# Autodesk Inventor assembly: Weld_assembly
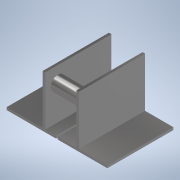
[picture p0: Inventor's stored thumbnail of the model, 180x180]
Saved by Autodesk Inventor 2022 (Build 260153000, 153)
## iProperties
Created: 2016-08
Part Number: Weld_assembly
Document SubType Name: Weldment
Designer: Gaurav
Weld Material: Welded Aluminum-6061
Mass: 881.351 g
Surface Area: 216.92 cm^2
Volume: 1 cm^3
Density: 881.351 g/cm^3
Author: Gaurav
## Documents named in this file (3)
- F:\My Data\Books_Final Books\2021_Books\Autodesk_Inventor_2022_Black_Book Folder\Autodesk Inventor_Resources_Student\Chapter 11\Weld_assembly.iam
- F:\My Data\Books_Final Books\2021_Books\Autodesk_Inventor_2022_Black_Book Folder\Autodesk Inventor_Resources_Student\Chapter 11\Plate.ipt
- F:\My Data\Books_Final Books\2021_Books\Autodesk_Inventor_2022_Black_Book Folder\Autodesk Inventor_Resources_Student\Chapter 11\Rod.ipt
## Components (5 placed, 2 different names)
1. Plate:1 — Mate:1, Flush:1, Flush:2, Mate:3, Flush:4
2. Plate:2 — Mate:1, Flush:1, Flush:2, Mate:2, Flush:3
3. Plate:3 — Mate:2, Flush:3, Mate:4
4. Plate:4 — Mate:3, Flush:4, Mate:5
5. Rod:1 — Mate:4, Mate:5
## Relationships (9: Mate 5, Flush 4)
- Mate:1: Plate:1 ↔ Plate:2
- Flush:1: Plate:1 ↔ Plate:2
- Flush:2: Plate:1 ↔ Plate:2
- Mate:2: Plate:2 ↔ Plate:3
- Flush:3: Plate:2 ↔ Plate:3
- Mate:3: Plate:1 ↔ Plate:4
- Flush:4: Plate:1 ↔ Plate:4
- Mate:4: Plate:3 ↔ Rod:1
- Mate:5: Plate:4 ↔ Rod:1
